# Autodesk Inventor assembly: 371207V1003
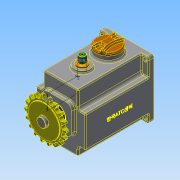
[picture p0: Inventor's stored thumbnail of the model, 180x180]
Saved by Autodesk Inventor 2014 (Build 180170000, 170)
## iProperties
Created: 2017-12
Part Number: 371207V1003
Document SubType Name: Assembly
Designer: 학생용
Mass: 2727.65 g
Surface Area: 2015.6 cm^2
Volume: 733.197 cm^3
Density: 3.72021 g/cm^3
Author: 학생용
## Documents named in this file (17)
- C:\Users\학생용\Desktop\371207V1003\371207V1003.iam
- C:\Users\학생용\Desktop\371207V1003\본체.ipt
- C:\Users\학생용\Desktop\371207V1003\가변스프링.ipt
- C:\Users\학생용\Desktop\371207V1003\멈춤나사 M3x8.ipt
- C:\Users\학생용\Desktop\371207V1003\메인축.ipt
- C:\Users\학생용\Desktop\371207V1003\베어링 608.ipt
- C:\Users\학생용\Desktop\371207V1003\베어링 6003.ipt
- C:\Users\학생용\Desktop\371207V1003\볼트 M4 x 10.ipt
- C:\Users\학생용\Desktop\371207V1003\부시.ipt
- C:\Users\학생용\Desktop\371207V1003\상부 캡.ipt
- C:\Users\학생용\Desktop\371207V1003\서브축.ipt
- C:\Users\학생용\Desktop\371207V1003\스프로킷.ipt
- C:\Users\학생용\Desktop\371207V1003\슬라이더.ipt
- C:\Users\학생용\Desktop\371207V1003\오일 실 8 22 7.ipt
- C:\Users\학생용\Desktop\371207V1003\오일 실 17 32 8.ipt
- C:\Users\학생용\Desktop\371207V1003\커버.ipt
- C:\Users\학생용\Desktop\371207V1003\키 5 x 5 x 18.ipt
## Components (1 placed, 1 different names)
1. 가변스프링:1
